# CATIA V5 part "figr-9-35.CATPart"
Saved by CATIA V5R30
Part number: Part1
Bounding box of the stored display mesh (mm): x -250 to 0, y -60 to 60, z 0 to 100
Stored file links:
  D:\PROJECTS\CATIA V56R 2020\Resources\Parts File\c09_catia_v5_6r2020_prt\figr-9-35.CATPart
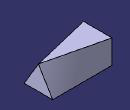
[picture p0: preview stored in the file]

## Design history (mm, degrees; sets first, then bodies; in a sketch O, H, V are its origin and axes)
Body1 (main body)
  Sketch1 on yz-plane, origin (0, 0, 0), H (0, 1, 0), V (0, 0, 1)
    point P1 (-60, 0)
    line L1 (-60, 0) -> (0, 100)
    point P2 (0, 100)
    line L2 (0, 100) -> (60, 0)
    point P3 (60, 0)
    line L3 (60, 0) -> (-60, 0)
    coincidence: P1 H, P2 V, P3 H
    horizontal: L3 H
    midpoint: O L3
  Sketch2, origin (-250, 0, 0), H (0, 1, 0), V (0, 0, 1)
    point P1 (-60, 0)
    line L1 (-60, 0) -> (60, 0)
    line L2 (60, 0) -> (60, 100)
    line L3 (60, 100) -> (-60, 100)
    line L4 (-60, 100) -> (-60, 0)
    coincidence: P1 H
    horizontal: L1 H, L3 H
    vertical: L2 V, L4 V
  Loft1: Sections (Sketch1; Sketch2), SectionCouplingPoints ({coupling CouplingPoints (vertex [element of Sketch1 | element of Sketch1]; vertex [element of Sketch2 | element of Sketch2])}; {coupling CouplingPoints (vertex [element of Sketch1 | element of Sketch1]; vertex [element of Sketch2 | element of Sketch2])}; {coupling CouplingPoints (vertex [element of Sketch1 | element of Sketch1]; vertex [element of Sketch2 | element of Sketch2])})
